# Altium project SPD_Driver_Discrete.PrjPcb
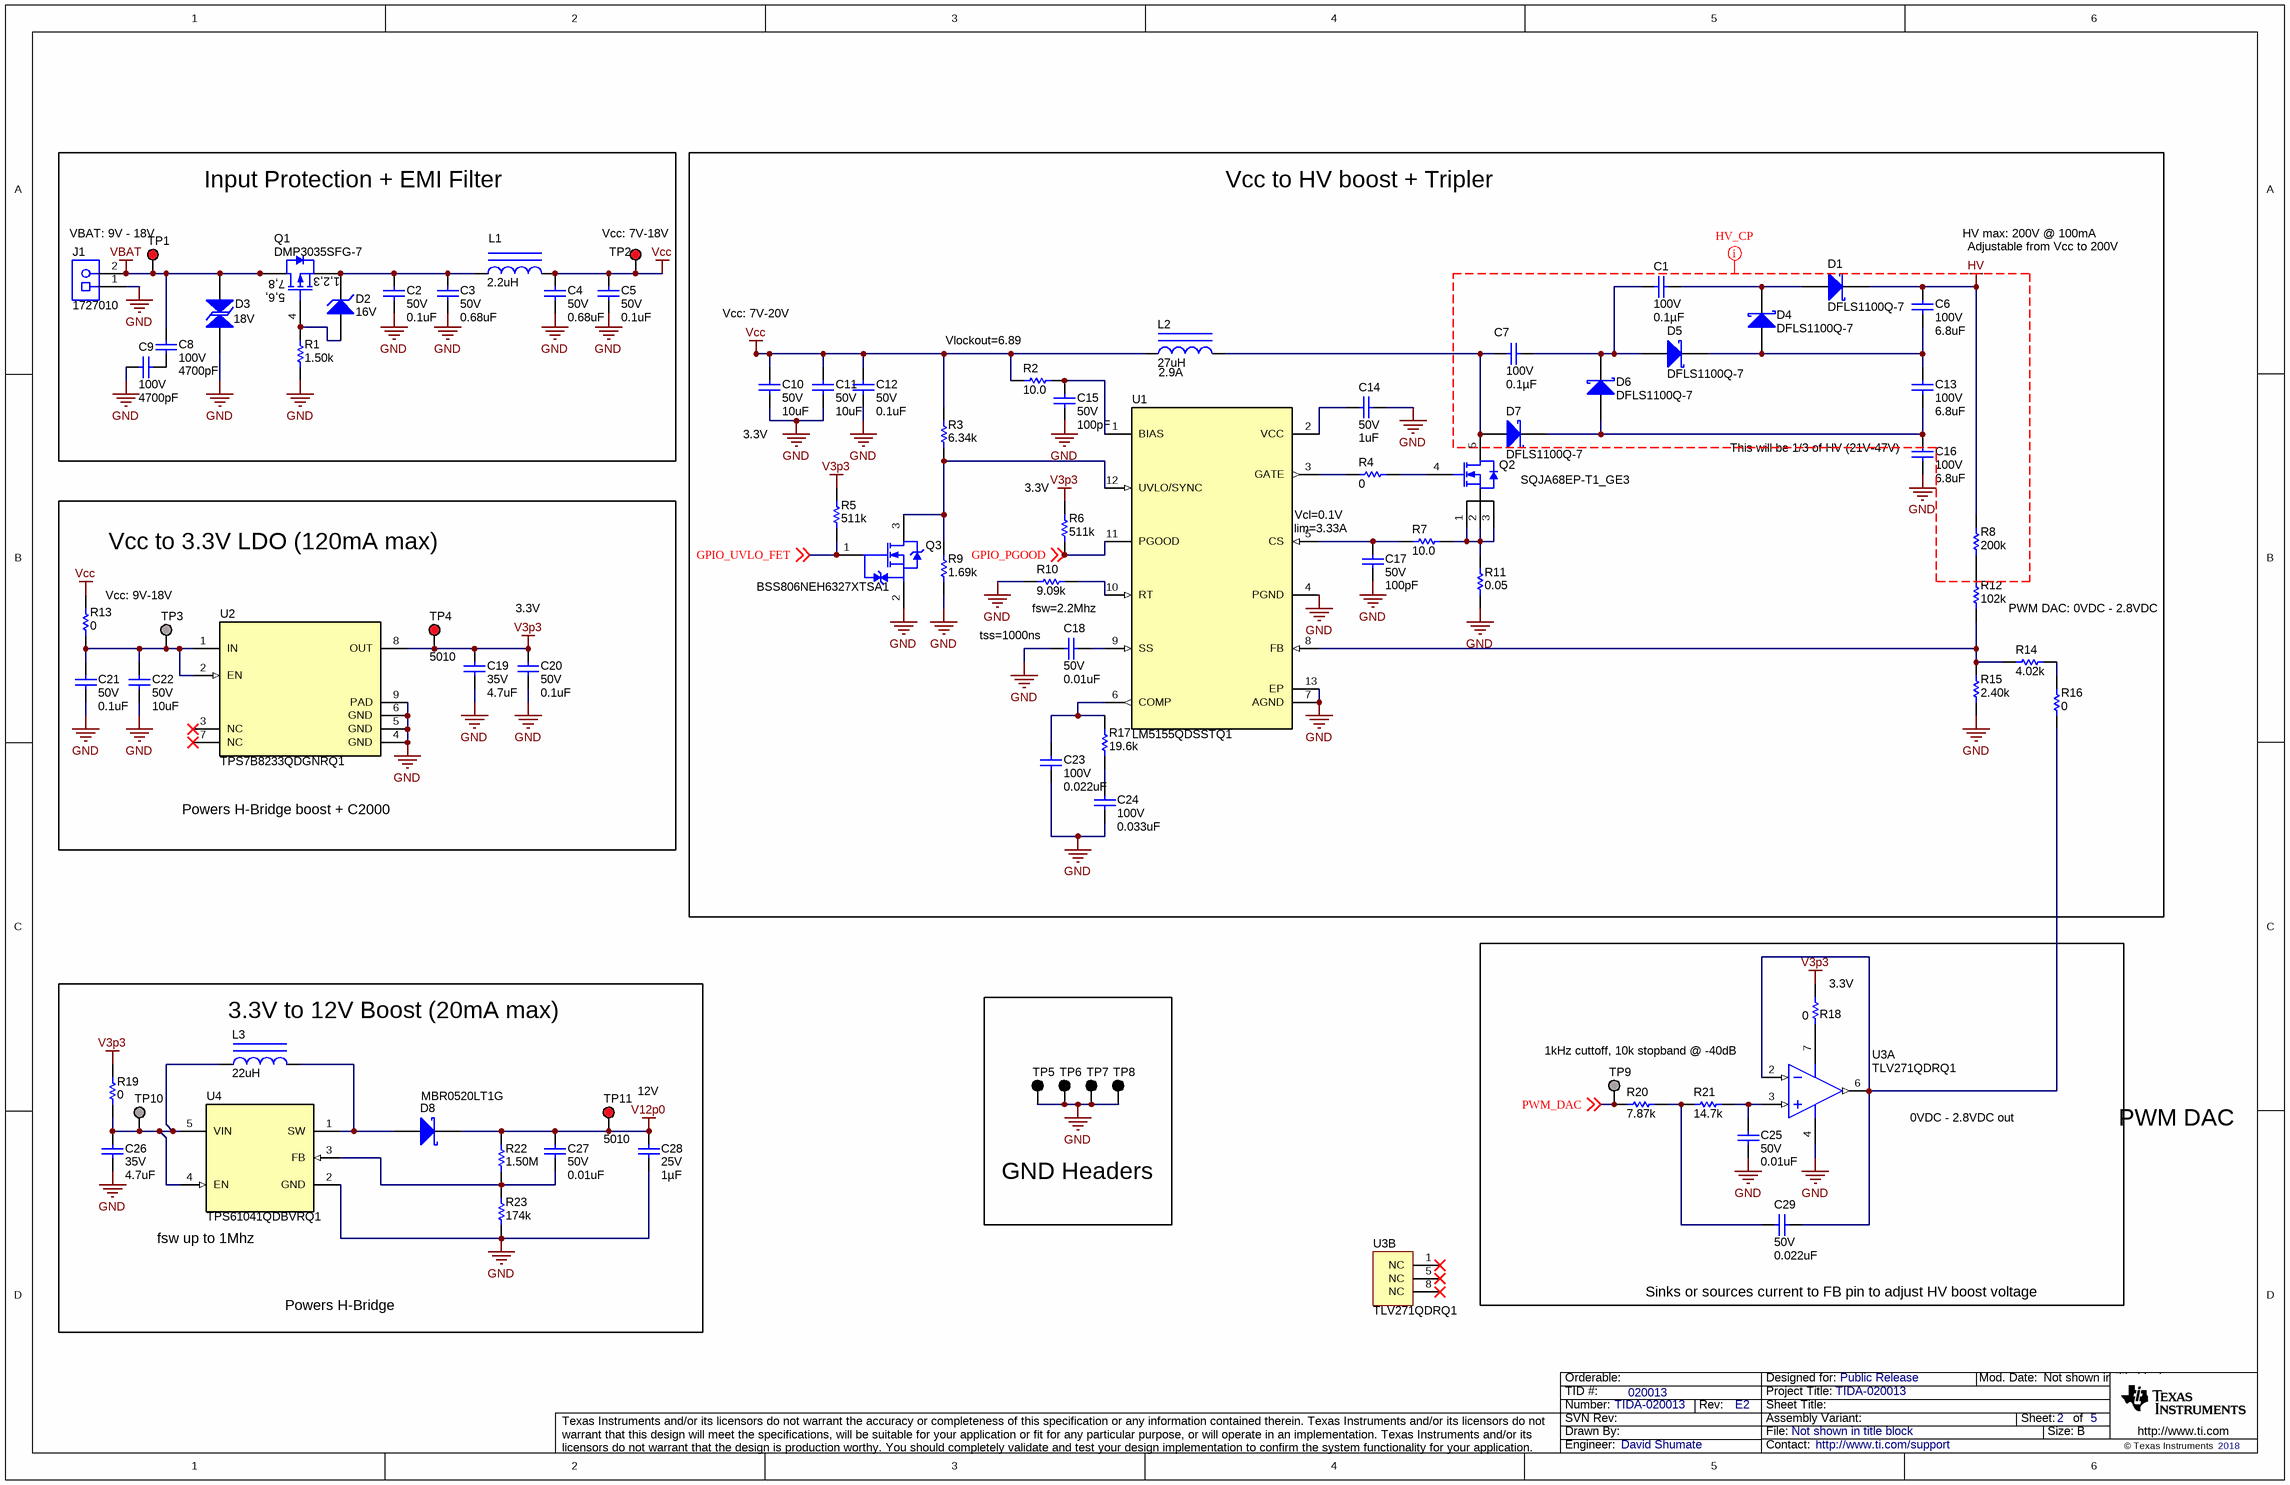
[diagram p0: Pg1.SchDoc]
CopyrightYear: 2018; PCB_Layout: David Shumate; PCB_Rev: E2; PRJ_Customer: Public Release; PRJ_Engineer: David Shumate; PRJ_Number: TIDA-020013; PRJ_Title: TIDA-020013; SCH_Rev: E2; TechSupport: http://www.ti.com/support; TID: 020013
4 sheets, 159 parts. Net scope: global (net labels, ports and power ports of the same name join across sheets).
Board file: PCB.PcbDoc
Sheets:
  Pg1.SchDoc
  Pg2.SchDoc
  Pg3.SchDoc
  EVM_Hardware.SchDoc

## Sheet Pg1.SchDoc
size 431 x 279 mm; Date: Not shown in title block; ApprovedBy: Not shown in title block; CheckedBy: Not shown in title block; Author: Not shown in title block; CompanyName: Not shown in title block; Engineer: Not shown in title block; Organization: Not shown in title block; Address1: Not shown in title block; Address2: Not shown in title block; Address3: Not shown in title block; Address4: Not shown in title block; DocumentNumber: 1; Revision: Use project parameter SCH_Rev; SheetNumber: 2; SheetTotal: 5; PageSetup: Record=PageOptions¦CenterHorizontal=True¦CenterVertical=True¦PrintScale=1.00¦XCorrection=1.00¦YCorrection=1.00¦PrintKind=0¦BorderSize=5000000¦LeftOffset=0¦BottomOffset=0¦Orientation=2¦PaperLength=1000¦PaperWidth=1000¦Scale=100¦PaperSource=15¦PrintQuality=600¦MediaType=1¦DitherType=10¦PaperKind=Letter¦PrintScaleMode=1

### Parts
C1  VDC_V: 100V  ValueDisplayed: 0.1µF  [0603]  (hidden comment: HMK107B7104KAHT)
C2  VDC_V: 50V  ValueDisplayed: 0.1uF  [0402]  (hidden comment: GCM155R71H104KE02D)
C3  VDC_V: 50V  ValueDisplayed: 0.68uF  [0805_HV]  (hidden comment: CGA4J3X7R1H684K125AB)
C4  VDC_V: 50V  ValueDisplayed: 0.68uF  [0805_HV]  (hidden comment: CGA4J3X7R1H684K125AB)
C5  VDC_V: 50V  ValueDisplayed: 0.1uF  [0402]  (hidden comment: GCM155R71H104KE02D)
C6  VDC_V: 100V  ValueDisplayed: 6.8uF  [2220_220]  (hidden comment: CGA9M3X7S2A685K200KB)
C7  VDC_V: 100V  ValueDisplayed: 0.1µF  [0603]  (hidden comment: HMK107B7104KAHT)
C8  VDC_V: 100V  ValueDisplayed: 4700pF  [0603L]  (hidden comment: CGA3E2X7R2A472K080AA)
C9  VDC_V: 100V  ValueDisplayed: 4700pF  [0603L]  (hidden comment: CGA3E2X7R2A472K080AA)
C10  VDC_V: 50V  ValueDisplayed: 10uF  [1206]  (hidden comment: CGA5L3X5R1H106M160AB)
C11  VDC_V: 50V  ValueDisplayed: 10uF  [1206]  (hidden comment: CGA5L3X5R1H106M160AB)
C12  VDC_V: 50V  ValueDisplayed: 0.1uF  [0402]  (hidden comment: GCM155R71H104KE02D)
C13  VDC_V: 100V  ValueDisplayed: 6.8uF  [2220_220]  (hidden comment: CGA9M3X7S2A685K200KB)
C14  VDC_V: 50V  ValueDisplayed: 1uF  [0805_HV1]  (hidden comment: CGA4J3X7R1H105K125AB)
C15  VDC_V: 50V  ValueDisplayed: 100pF  [0603L]  (hidden comment: CGA3E2NP01H101J080AA)
C16  VDC_V: 100V  ValueDisplayed: 6.8uF  [2220_220]  (hidden comment: CGA9M3X7S2A685K200KB)
C17  VDC_V: 50V  ValueDisplayed: 100pF  [0603L]  (hidden comment: CGA3E2NP01H101J080AA)
C18  VDC_V: 50V  ValueDisplayed: 0.01uF  [0402L]  (hidden comment: CGA2B3X7R1H103K050BB)
C19  VDC_V: 35V  ValueDisplayed: 4.7uF  [0805_HV]  (hidden comment: CGA4J1X7R1V475K125AC)
C20  VDC_V: 50V  ValueDisplayed: 0.1uF  [0402]  (hidden comment: GCM155R71H104KE02D)
C21  VDC_V: 50V  ValueDisplayed: 0.1uF  [0402]  (hidden comment: GCM155R71H104KE02D)
C22  VDC_V: 50V  ValueDisplayed: 10uF  [1206]  (hidden comment: CGA5L3X5R1H106M160AB)
C23  VDC_V: 100V  ValueDisplayed: 0.022uF  [0603L]  (hidden comment: CGA3E2X7R2A223K080AA)
C24  VDC_V: 100V  ValueDisplayed: 0.033uF  [0603L]  (hidden comment: CGA3E3X7S2A333K080AB)
C25  VDC_V: 50V  ValueDisplayed: 0.01uF  [0402]  (hidden comment: CGA2B3X7R1H103K050BB)
C26  VDC_V: 35V  ValueDisplayed: 4.7uF  [0805_HV]  (hidden comment: CGA4J1X7R1V475K125AC)
C27  VDC_V: 50V  ValueDisplayed: 0.01uF  [0402]  (hidden comment: CGA2B3X7R1H103K050BB)
C28  VDC_V: 25V  ValueDisplayed: 1µF  [0603S]  (hidden comment: CGA3E1X7R1E105K080AC)
C29  VDC_V: 50V  ValueDisplayed: 0.022uF  [0402]  (hidden comment: CGA2B3X7R1H223K050BB)
D1  DFLS1100Q-7  [PowerDI123]
D2  value 16V  [SOD-123]  (hidden comment: BZT52C16-7-F)
D3  value 18V  [SMA]  (hidden comment: P4SMA18CA-E3/61)
D4  DFLS1100Q-7  [PowerDI123]
D5  DFLS1100Q-7  [PowerDI123]
D6  DFLS1100Q-7  [PowerDI123]
D7  DFLS1100Q-7  [PowerDI123]
D8  MBR0520LT1G  [SOD-123]
J1  1727010  [PhoenixConact_1727010]
L1  ValueDisplayed: 2.2uH  [XAL5030]  (hidden comment: XAL5030-222MEB)
L2  Value2: 2.9A  ValueDisplayed: 27uH  [MSS1260T]  (hidden comment: MSS1260T-273MLB)
L3  ValueDisplayed: 22uH  [WE-MAIA_3015]  (hidden comment: 78438335220)
Q1  DMP3035SFG-7  [PowerDI3333-8]
Q2  SQJA68EP-T1_GE3  [PowerPAK_SO-8L]
Q3  BSS806NEH6327XTSA1  [SOT-23L]
R1  ValueDisplayed: 1.50k  [0603L]  (hidden comment: CRCW06031K50FKEA)
R2  ValueDisplayed: 10.0  [0603]  (hidden comment: CRCW060310R0FKEAHP)
R3  ValueDisplayed: 6.34k  [0402]  (hidden comment: CRCW04026K34FKED)
R4  ValueDisplayed: 0  [0603L]  (hidden comment: RCS06030000Z0EA)
R5  ValueDisplayed: 511k  [0402]  (hidden comment: CRCW0402511KFKED)
R6  ValueDisplayed: 511k  [0402]  (hidden comment: CRCW0402511KFKED)
R7  ValueDisplayed: 10.0  [0603L]  (hidden comment: CRCW060310R0FKEAHP)
R8  ValueDisplayed: 200k  [1206L]  (hidden comment: ERJ-8ENF2003V)
R9  ValueDisplayed: 1.69k  [0805_HV1]  (hidden comment: ERJ-6ENF1691V)
R10  ValueDisplayed: 9.09k  [0603L]  (hidden comment: CRCW06039K09FKEA)
R11  ValueDisplayed: 0.05  [0603L]  (hidden comment: ERJ-L03KF50MV)
R12  ValueDisplayed: 102k  [1206L]  (hidden comment: ERJ-8ENF1023V)
R13  ValueDisplayed: 0  [0603]  (hidden comment: RCS06030000Z0EA)
R14  ValueDisplayed: 4.02k  [0603L]  (hidden comment: CRCW06034K02FKEA)
R15  ValueDisplayed: 2.40k  [0402L]  (hidden comment: ERJ-2RKF2401X)
R16  ValueDisplayed: 0  [0402L]  (hidden comment: CRCW04020000Z0EDHP)
R17  ValueDisplayed: 19.6k  [0603L]  (hidden comment: CRCW060319K6FKEA)
R18  ValueDisplayed: 0  [0402]  (hidden comment: CRCW04020000Z0EDHP)
R19  ValueDisplayed: 0  [0603]  (hidden comment: RCS06030000Z0EA)
R20  ValueDisplayed: 7.87k  [0402]  (hidden comment: CRCW04027K87FKED)
R21  ValueDisplayed: 14.7k  [0402]  (hidden comment: CRCW040214K7FKED)
R22  ValueDisplayed: 1.50M  [0402]  (hidden comment: CRCW04021M50FKED)
R23  ValueDisplayed: 174k  [0402]  (hidden comment: CRCW0402174KFKED)
TP1  5010  [Keystone5010]  (value not drawn)
TP2  5010  [Keystone5010]  (value not drawn)
TP3  TP_SM_1MM  [TP_SM_1MM]  (value not drawn)  (no BOM)
TP4  5010  [Keystone5010]
TP5  5011  [Keystone5011]  (value not drawn)
TP6  5011  [Keystone5011]  (value not drawn)
TP7  5011  [Keystone5011]  (value not drawn)
TP8  5011  [Keystone5011]  (value not drawn)
TP9  TP_SM_1MM  [TP_SM_1MM]  (value not drawn)  (no BOM)
TP10  TP_SM_1MM  [TP_SM_1MM]  (value not drawn)  (no BOM)
TP11  5010  [Keystone5010]
U1  LM5155QDSSTQ1  [DSS0012C]
U2  TPS7B8233QDGNRQ1  [DGN0008D_N]
U3  TLV271QDRQ1  [D0008A_N]  (parts A,B of 2)
U4  TPS61041QDBVRQ1  [DBV0005A_N]

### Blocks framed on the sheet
Input Protection + EMI Filter: C2-C5 C8 C9 D2 D3 J1 L1 Q1 R1 TP1 TP2
Vcc to HV boost + Tripler: C1 C6 C7 C10-C18 C23 C24 D1 D4-D7 L2 Q2 Q3 R2-R12 R14-R17 U1
Vcc to 3.3V LDO (120mA max): C19-C22 R13 TP3 TP4 U2
3.3V to 12V Boost (20mA max): C26-C28 D8 L3 R19 R22 R23 TP10 TP11 U4
GND Headers: TP5-TP8

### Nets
GND: C2.2 C3.2 C4.2 C5.2 C9.1 C10.2 C11.2 C12.2 C14.1 C15.2 C16.2 C17.2 C18.2 C19.2 C20.2 C21.2 C22.2 C23.2 C24.2 C25.2 C26.2 C28.2 D3.2 J1.1 Q3.2(S) R1.1 R9.1 R10.1 R11.1 R15.1 R23.1 TP5.1 TP6.1 TP7.1 TP8.1 U1.4(PGND) U1.7(AGND) U1.13(EP) U2.4(GND) U2.5(GND) U2.6(GND) U2.9(PAD) U3.4(GND) U4.2(GND)
HV: C6.1 D1.1(K) R8.2
V3p3: C19.1 C20.1 R5.2 R6.2 R18.2 R19.2 TP4.1 U2.8(OUT)
V12p0: C27.1 C28.1 D8.1(K) R22.2 TP11.1
VBAT: C8.1 D3.1 J1.2 Q1.5(D) Q1.6(D) Q1.7(D) Q1.8(D) Q1.9(D) TP1.1
Vcc: C4.1 C5.1 C10.1 C11.1 C12.1 L1.2 L2.1 R2.1 R3.2 R13.2 TP2.1
GPIO_PGOOD: R6.1 U1.11(PGOOD) ; off-sheet GPIO_PGOOD
GPIO_UVLO_FET: Q3.1(G) R5.1 ; off-sheet GPIO_UVLO_FET
PWM_DAC: R20.1 TP9.1 ; off-sheet PWM_DAC
NetC1_1: C1.1 D1.2(A) D4.1(K)
NetC1_2: C1.2 C7.1 D5.2(A) D6.1(K)
NetC2_1: C2.1 C3.1 D2.1(K) L1.1 Q1.1(S) Q1.2(S) Q1.3(S)
NetC6_2: C6.2 C13.1 D4.2(A) D5.1(K)
NetC7_2: C7.2 D7.2(A) L2.2 Q2.5(D)
NetC8_2: C8.2 C9.2
NetC13_2: C13.2 C16.1 D6.2(A) D7.1(K)
NetC14_2: C14.2 U1.2(VCC)
NetC15_1: C15.1 R2.2 U1.1(BIAS)
NetC17_1: C17.1 R7.1 U1.5(CS)
NetC18_1: C18.1 U1.9(SS)
NetC21_1: C21.1 C22.1 R13.1 TP3.1 U2.1(IN) U2.2(EN)
NetC23_1: C23.1 R17.2 U1.6(COMP)
NetC24_1: C24.1 R17.1
NetC25_1: C25.1 R21.2 U3.3(IN+)
NetC26_1: C26.1 L3.1 R19.1 TP10.1 U4.4(EN) U4.5(VIN)
NetC27_2: C27.2 R22.1 R23.2 U4.3(FB)
NetC29_1: C29.1 R16.1 U3.2(IN-) U3.6(OUT)
NetC29_2: C29.2 R20.2 R21.1
NetD2_2: D2.2(A) Q1.4(G) R1.2
NetD8_2: D8.2(A) L3.2 U4.1(SW)
NetQ2_1: Q2.1(S) Q2.2(S) Q2.3(S) R7.2 R11.2
NetQ2_4: Q2.4(G) R4.2
NetQ3_3: Q3.3(D) R3.1 R9.2 U1.12(UVLO/SYNC)
NetR4_1: R4.1 U1.3(GATE)
NetR8_1: R8.1 R12.2
NetR10_2: R10.2 U1.10(RT)
NetR12_1: R12.1 R14.1 R15.2 U1.8(FB)
NetR14_2: R14.2 R16.2
NetR18_1: R18.1 U3.7(VDD)

Not connected (* = marked no-connect by the designer): U2 3(NC)* 7(NC)*; U3 1(NC)* 5(NC)* 8(NC)*

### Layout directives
net class HV_CP: GND, HV

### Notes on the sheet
- VBAT: 9V - 18V
- (near TP2) Vcc: 7V-18V
- HV max: 200V @ 100mA
- Adjustable from Vcc to 200V
- Vcc: 7V-20V
- (near R2) Vlockout=6.89
- (near C10) 3.3V
- (near R6) 3.3V
- (near C16) This will be 1/3 of HV (21V-47V)
- (near U1) Vcl=0.1V
- (near U1) Ilim=3.33A
- Vcc: 9V-18V
- 3.3V
- (near C18) tss=1000ns
- fsw=2.2Mhz
- PWM DAC: 0VDC - 2.8VDC
- Powers H-Bridge boost + C2000
- (near R18) 3.3V
- 12V
- 1kHz cuttoff, 10k stopband @ -40dB
- 0VDC - 2.8VDC out
- PWM DAC
- (near U4) fsw up to 1Mhz
- Powers H-Bridge
- Sinks or sources current to FB pin to adjust HV boost voltage

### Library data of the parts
C1 C7 = CMP-0081011-1: CAP, CERM, 0.1 µF, 100 V,+/- 10%, X7R, AEC-Q200 Grade 1, 0603; Manufacturer: Taiyo Yuden; Cap_F: 100nF; SizeAreaWB_mm2: 4.68; SizeArea_mm2: 1.28; AEC Qualified: Y; AEC Category: Q200; Value: 0.1uF; TaMax_C: 125°C; SizeZ_mm: 1; Polarized: N; TaMin_C: -55°C; SizeY_mm: 0.8; U/M: EA; SizeX_mm: 1.6
C2 C5 = CMP-0006356-2: CAP, CERM, 0.1 uF, 50 V, +/- 10%, X7R, AEC-Q200 Grade 1, 0402; Manufacturer: MuRata; TaMin_C: -55°C; Polarized: N; SizeAreaWB_mm2: 3; Value1: Unknown; U/M: EA; Value: 0.1uF; TaMax_C: 125°C; SizeZ_mm: 0.6; SizeX_mm: 1; SizeY_mm: 0.5; CompType: Capacitor; AEC Qualified: Y; Cap_F: 100nF; AEC Category: Q200
C3 C4 = CMP-0007979-2: CAP, CERM, 0.68 uF, 50 V, +/- 10%, X7R, AEC-Q200 Grade 1, 0805; Manufacturer: TDK; TaMin_C: -55°C; ESR_ohm: 0.011711; Polarized: N; SizeAreaWB_mm2: 6.75; Value1: 0.011711 ohm; U/M: EA; Value: 0.68uF; TaMax_C: 125°C; SizeZ_mm: 1.45; SizeX_mm: 2; SizeY_mm: 1.25; Cap_Case: 0805; SizeArea_mm2: 2.5; CompType: Capacitor; AEC Qualified: Y; Cap_F: 680nF; IRMS_A: 1.91098A; AEC Grade: 1; AEC Category: Q200
C6 C13 C16 = CMP-0009407-2: CAP, CERM, 6.8 uF, 100 V, +/- 10%, X7S, AEC-Q200 Grade 1, 2220; Manufacturer: TDK; TaMin_C: -55°C; ESR_ohm: 3.492m; Polarized: N; SizeAreaWB_mm2: 53.9; Value1: 0.003492 ohm; U/M: EA; Value: 6.8uF; TaMax_C: 125°C; SizeZ_mm: 2.2; SizeX_mm: 5.7; SizeY_mm: 5; SizeArea_mm2: 28.5; AEC Qualified: Y; Cap_F: 6.8µF; IRMS_A: 4.88574A; AEC Grade: 1; AEC Category: Q200
C8 C9 = CMP-0007088-4: CAP, CERM, 4700 pF, 100 V, +/- 10%, X7R, AEC-Q200 Grade 1, 0603; Manufacturer: TDK; TaMin_C: -55°C; ESR_ohm: 4.69862d; Polarized: N; SizeAreaWB_mm2: 4.68; Value1: 0.469862 ohm; U/M: EA; Value: 4700pF; TaMax_C: 125°C; SizeZ_mm: 1; SizeX_mm: 1.6; SizeY_mm: 0.8; Cap_Case: 0603; SizeArea_mm2: 1.28; CompType: Capacitor; AEC Qualified: Y; Cap_F: 4.7nF; IRMS_A: 3.2335dA; AEC Category: Q200
C10 C11 C22 = CMP-0008785-2: CAP, CERM, 10 uF, 50 V, +/- 20%, X5R, AEC-Q200 Grade 3, 1206; Manufacturer: TDK; TaMin_C: -55°C; Polarized: N; SizeAreaWB_mm2: 10.92; Value1: Unknown; U/M: EA; Value: 10uF; TaMax_C: 85°C; SizeZ_mm: 1.35; SizeX_mm: 3.2; SizeY_mm: 1.6; SizeArea_mm2: 5.12; CompType: Capacitor; AEC Qualified: Y; Cap_F: 10µF; AEC Grade: 3; AEC Category: Q200
C12 C20 C21 = CMP-0006356-2: CAP, CERM, 0.1 uF, 50 V, +/- 10%, X7R, AEC-Q200 Grade 1, 0402; Manufacturer: MuRata; TaMin_C: -55°C; Polarized: N; SizeAreaWB_mm2: 3; Value1: Unknown; U/M: EA; Value: 0.1uF; TaMax_C: 125°C; SizeZ_mm: 0.6; SizeX_mm: 1; SizeY_mm: 0.5; AEC Qualified: Y; Cap_F: 100nF; AEC Category: Q200
C14 = CMP-0007976-2: CAP, CERM, 1 uF, 50 V, +/- 10%, X7R, AEC-Q200 Grade 1, 0805; Manufacturer: TDK; TaMin_C: -55°C; ESR_ohm: 8.782m; Polarized: N; SizeAreaWB_mm2: 6.75; Value1: 0.008782 ohm; U/M: EA; Value: 1uF; TaMax_C: 125°C; SizeZ_mm: 1.45; SizeX_mm: 2; SizeY_mm: 1.25; Cap_Case: 0805; SizeArea_mm2: 2.5; CompType: Capacitor; AEC Qualified: Y; Cap_F: 1µF; IRMS_A: 2.20488A; AEC Grade: 1; AEC Category: Q200
C15 C17 = CMP-0007075-4: CAP, CERM, 100 pF, 50 V, +/- 5%, C0G/NP0, AEC-Q200 Grade 0, 0603; Manufacturer: TDK; TaMin_C: -55°C; Polarized: N; SizeAreaWB_mm2: 4.68; Value1: Unknown; U/M: EA; Value: 100pF; TaMax_C: 150°C; SizeZ_mm: 1; SizeX_mm: 1.6; SizeY_mm: 0.8; Cap_Case: 0603; SizeArea_mm2: 1.28; CompType: Capacitor; AEC Qualified: Y; AEC Grade: 0; AEC Category: Q200
C18 = CMP-0006324-2: CAP, CERM, 0.01 uF, 50 V, +/- 10%, X7R, AEC-Q200 Grade 1, 0402; Manufacturer: TDK; TaMin_C: -55°C; ESR_ohm: 3.33065d; Polarized: N; SizeAreaWB_mm2: 3; Value1: 0.333065 ohm; U/M: EA; Value: 0.01uF; TaMax_C: 125°C; SizeZ_mm: 0.6; SizeX_mm: 1; SizeY_mm: 0.5; Cap_Case: 0402; CompType: Capacitor; AEC Qualified: Y; Cap_F: 10nF; IRMS_A: 3.23373dA; AEC Category: Q200
C19 C26 = CMP-0007964-2: CAP, CERM, 4.7 uF, 35 V, +/- 10%, X7R, AEC-Q200 Grade 1, 0805; Manufacturer: TDK; TaMin_C: -55°C; ESR_ohm: 2.346m; Polarized: N; SizeAreaWB_mm2: 6.75; Value1: 0.002346 ohm; U/M: EA; Value: 4.7uF; TaMax_C: 125°C; SizeZ_mm: 1.45; SizeX_mm: 2; SizeY_mm: 1.25; Cap_Case: 0805; SizeArea_mm2: 2.5; AEC Qualified: Y; Cap_F: 4.7µF; IRMS_A: 4.26021A; AEC Grade: 1; AEC Category: Q200
C23 = CMP-0007086-4: CAP, CERM, 0.022 uF, 100 V, +/- 10%, X7R, AEC-Q200 Grade 1, 0603; Manufacturer: TDK; TaMin_C: -55°C; ESR_ohm: 0.083542; Polarized: N; SizeAreaWB_mm2: 4.68; Value1: 0.083542 ohm; U/M: EA; TaMax_C: 125°C; SizeZ_mm: 1; SizeX_mm: 1.6; SizeY_mm: 0.8; Cap_Case: 0603; SizeArea_mm2: 1.28; CompType: Capacitor; AEC Qualified: Y; Cap_F: 22nF; IRMS_A: 6.09312dA; AEC Category: Q200
C24 = CMP-0007100-4: CAP, CERM, 0.033 uF, 100 V, +/- 10%, X7S, AEC-Q200 Grade 1, 0603; Manufacturer: TDK; TaMin_C: -55°C; ESR_ohm: 1.39637d; Polarized: N; SizeAreaWB_mm2: 4.68; Value1: 0.139637 ohm; U/M: EA; TaMax_C: 125°C; SizeZ_mm: 1; SizeX_mm: 1.6; SizeY_mm: 0.8; Cap_Case: 0603; SizeArea_mm2: 1.28; CompType: Capacitor; AEC Qualified: Y; Cap_F: 33nF; IRMS_A: 4.62257dA; AEC Category: Q200
C25 C27 = CMP-0006324-2: CAP, CERM, 0.01 uF, 50 V, +/- 10%, X7R, AEC-Q200 Grade 1, 0402; Manufacturer: TDK; TaMin_C: -55°C; ESR_ohm: 3.33065d; Polarized: N; SizeAreaWB_mm2: 3; Value1: 0.333065 ohm; U/M: EA; Value: 0.01uF; TaMax_C: 125°C; SizeZ_mm: 0.6; SizeX_mm: 1; SizeY_mm: 0.5; AEC Qualified: Y; Cap_F: 10nF; IRMS_A: 3.23373dA; AEC Category: Q200
C28 = CMP-0076705-3: CAP, CERM, 1 µF, 25 V,+/- 10%, X7R, AEC-Q200 Grade 1, 0603; Manufacturer: TDK; SizeAreaWB_mm2: 4.68; SizeArea_mm2: 1.28; AEC Qualified: Y; AEC Category: Q200; Value: 1uF; TaMax_C: 125°C; SizeZ_mm: 1.0; AEC Grade: 1; Polarized: N; TaMin_C: -55°C; SizeY_mm: 0.8; U/M: EA; SizeX_mm: 1.6; Cap_Case: 1.6x0.8x0.8mm
C29 = CMP-0006328-2: CAP, CERM, 0.022 uF, 50 V, +/- 10%, X7R, AEC-Q200 Grade 1, 0402; Manufacturer: TDK; TaMin_C: -55°C; ESR_ohm: 1.41987d; Polarized: N; SizeAreaWB_mm2: 3; Value1: 0.141987 ohm; U/M: EA; TaMax_C: 125°C; SizeZ_mm: 0.6; SizeX_mm: 1; SizeY_mm: 0.5; AEC Qualified: Y; Cap_F: 22nF; IRMS_A: 4.51393dA; AEC Category: Q200
D1 D4-D7 = CMP-0074797-1: Diode, Schottky, 100 V, 1 A, AEC-Q101, PowerDI123; Manufacturer: Diodes Inc.; Io_A: 1A; SizeAreaWB_mm2: 13.066; Vr_V: 100V; TJmax_C: 175°C; U/M: EA; Value: 100V; SizeZ_mm: 0.98; SizeX_mm: 3.7; SizeY_mm: 1.78; Vf_V: 7.7dV; Value2: .77V; SizeArea_mm2: 6.586; AEC Qualified: Y; AEC Category: Q101; RJC_CperW: 21.0
D2 = CMP-0005769-2: Diode, Zener, 16 V, 500 mW, AEC-Q101, SOD-123; Manufacturer: Diodes Inc.; Power_W: 500mW; SizeAreaWB_mm2: 13.095; Value1: 0.5W; RJA_CperW: 338; U/M: EA; SizeZ_mm: 1.35; SizeX_mm: 3.85; SizeY_mm: 1.7; SizeArea_mm2: 6.545; AEC Qualified: Y; AEC Category: Q101
D3 = CMP-0005445-2: Diode, TVS, Bi, 18 V, 25.2 Vc, AEC-Q101, SMA; Manufacturer: Vishay-Semiconductor; Power_W: 3.3W; SizeAreaWB_mm2: 37.3428; RJA_CperW: 120; U/M: EA; SizeZ_mm: 2.87; SizeX_mm: 5.59; SizeY_mm: 2.92; SizeArea_mm2: 16.3228; AEC Qualified: Y; AEC Category: Q101
D8 = CMP-0028524-1: Diode, Schottky, 20 V, 0.5 A, SOD-123; Manufacturer: ON Semiconductor; Io_A: 5dA; Green_Lifecycle: Active; SizeAreaWB_mm2: 13.095; Vr_V: 20V; Green_REACh: Passed; Value1: 0.5A; TJmax_C: 125°C; U/M: EA; Value: 20V; SizeZ_mm: 1.35; SizeX_mm: 3.85; SizeY_mm: 1.7; Vf_V: 3.85dV; Value2: 0.385V; SizeArea_mm2: 6.545; AEC Category: Q101; RJC_CperW: 150
J1 = CMP-0055472-1: Conn Term Block, 2POS, 3.81mm, TH; Manufacturer: Phoenix Contact; CT: TRUE; Green_REACh: Incomplete; CompType: Terminal Block; CNHeader: FALSE; Green_Lifecycle: Not Set
L1 = CMP-0061001-2: Inductor, Shielded, Composite, 2.2 µH, 9.2 A, 0.01 ohm, AEC-Q200 Grade 1, SMD; Manufacturer: Coilcraft; Isat: 12.9A @ 30% inductance drop; Irms: 9.2A @ 40C rise; Green_Lifecycle: Not Set; SizeAreaWB_mm2: 54.4544; DCR_ohm: 0.01; Green_REACh: Incomplete; Value: 2.2uH; Imax_A: 9.2A; SizeZ_mm: 3.1; SizeX_mm: 5.28; SizeY_mm: 5.48; SizeArea_mm2: 28.9344; Ind_H: 2.2µH; AEC Qualified: 1; AEC Category: Q200; AEC Grade: Y
L2 = CMP-0061500-2: Inductor, Shielded Drum Core, Ferrite, 27 uH, 2.9 A, 0.05 ohm, SMD; Manufacturer: Coilcraft; Isat: 4.68A @ 30% inductance drop; Irms: 2.9A @ 40C rise; Green_Lifecycle: Not Set; SizeAreaWB_mm2: 204.49; DCR_ohm: 0.05; Green_REACh: Incomplete; Value: 27uH; SizeZ_mm: 6; SizeX_mm: 12.3; SizeArea_mm2: 151.29; Ind_H: 27µH; AEC Category: Q200
L3 = CMP-0064681-2: Inductor, Shielded, Powdered Iron, 22 uH, 0.6 A, 1.04 ohm, AEC-Q200 Grade 1, SMD; Manufacturer: Wurth Elektronik; Isat: 1.6A @ 20% inductance drop; Irms: 0.6A @ 40C rise; SizeAreaWB_mm2: 16; DCR_ohm: 1.04; Value: 22uH; Imax_A: 6dA; SizeZ_mm: 1.5; SizeX_mm: 3; Value2: 0.6A; SizeArea_mm2: 9; Ind_H: 22µH; AEC Qualified: Y; AEC Grade: 1; AEC Category: Q200
Q1 = CMP-0000041-2: MOSFET, P-CH, -30 V, -8.5 A, AEC-Q101, 8-PowerVDFN; Alternate Manufacturer: None; Manufacturer: Diodes Inc.; SizeZ_mm: 0.8; ChType: P; Value2: 35.5 nC; VdsMax_V: -30V; SizeX_mm: 3.3; Vgs_V: -25V; QgTyp_nC: 35.5; AEC Qualified: Y; Value: -30V; SizeArea_mm2: 10.89; AEC Category: Q101; IdsMax_A: -8.5A; SizeAreaWB_mm2: 18.49; U/M: EA
Q2 = CMP-0080929-1: MOSFET, N-CH, 100 V, 14 A, AEC-Q101, PowerPAK_SO-8L; Alternate Manufacturer: None; Manufacturer: Vishay-Siliconix; Rdson45_ohm: 1.17d; QgTyp_nC: 4.7; SizeAreaWB_mm2: 58.1095; Vgs_V: 20V; Value1: 0.117 ohm; VdsMax_V: 100V; Value: 100V; IdsMax_A: 14A; SizeZ_mm: 1.14; SizeX_mm: 6.15; SizeY_mm: 5.13; Value2: 4.7 nC; SizeArea_mm2: 31.5495; ChType: N; AEC Qualified: Y; AEC Category: Q101
Q3 = CMP-0077248-1: MOSFET, N-CH, 20 V, 2.3 A, AEC-Q101, SOT-23; Manufacturer: Infineon Technologies; Alternate Manufacturer: None; ChType: N; QgTyp_nC: 1.7; SizeAreaWB_mm2: 14.0; SizeArea_mm2: 7.5; IdsMax_A: 2.3A; AEC Qualified: Y; VdsMax_V: 20V; Vgs_V: 8V; AEC Category: Q101; Value: 20V; SizeZ_mm: 1.1; SizeY_mm: 3.0; Value2: 1.7 nC; U/M: EA; Value1: ? ohm; SizeX_mm: 2.5
R1 = CMP-0022126-4: RES, 1.50 k, 1%, 0.1 W, AEC-Q200 Grade 0, 0603; Manufacturer: Vishay-Dale; Power_W: 100mW; TempCo: 100 ppm/C; Value_Code: 1k50; Value: 1.50k; EIA_Code: E96; Res_ohm: 1.5k; SizeX_mm: 1.6; SizeY_mm: 0.8; SizeZ_mm: 1; Value2: 0.1W; SizeArea_mm2: 1.28; CompType: Resistor; AEC Qualified: Y; VDC_V: 75V; AEC Category: Q200; AEC Grade: 0
R2 = CMP-0022004-4: RES, 10.0, 1%, 0.25 W, AEC-Q200 Grade 0, 0603; Manufacturer: Vishay-Dale; Power_W: 250mW; TempCo: 100 ppm/C; Value_Code: 10R0; Value: 10.0; EIA_Code: E96; Res_ohm: 10; SizeX_mm: 1.6; SizeY_mm: 0.8; SizeZ_mm: 1; Value2: 0.25W; SizeArea_mm2: 1.28; AEC Qualified: Y; VDC_V: 75V; AEC Category: Q200; AEC Grade: 0
R3 = CMP-0026514-2: RES, 6.34 k, 1%, 0.063 W, AEC-Q200 Grade 0, 0402; Manufacturer: Vishay-Dale; Power_W: 63mW; TempCo: 100 ppm/C; Value_Code: 6k34; Value: 6.34k; EIA_Code: E96; SizeX_mm: 1; SizeY_mm: 0.5; SizeZ_mm: 0.6; Value2: 0.063W; AEC Qualified: Y; VDC_V: 50V; AEC Category: Q200; AEC Grade: 0
R4 = CMP-0081973-1: RES, 0, 0%, 0.25 W, AEC-Q200 Grade 0, 0603; Manufacturer: Vishay-Dale; SizeAreaWB_mm2: 4.68; SizeArea_mm2: 1.28; AEC Qualified: Y; AEC Category: Q200; Value: 0; SizeZ_mm: 1; SizeY_mm: 0.8; Power_W: 250mW; Value2: 0.25W; CompType: Resistor; SizeX_mm: 1.6
R5 R6 = CMP-0026435-2: RES, 511 k, 1%, 0.063 W, AEC-Q200 Grade 0, 0402; Manufacturer: Vishay-Dale; Power_W: 63mW; TempCo: 100 ppm/C; Value: 511k; EIA_Code: E96; SizeX_mm: 1; SizeY_mm: 0.5; SizeZ_mm: 0.6; Value2: 0.063W; AEC Qualified: Y; VDC_V: 50V; AEC Category: Q200; AEC Grade: 0
R7 = CMP-0022004-4: RES, 10.0, 1%, 0.25 W, AEC-Q200 Grade 0, 0603; Manufacturer: Vishay-Dale; Power_W: 250mW; TempCo: 100 ppm/C; Value_Code: 10R0; Value: 10.0; EIA_Code: E96; Res_ohm: 10; SizeX_mm: 1.6; SizeY_mm: 0.8; SizeZ_mm: 1; Value2: 0.25W; SizeArea_mm2: 1.28; CompType: Resistor; AEC Qualified: Y; VDC_V: 75V; AEC Category: Q200; AEC Grade: 0
R8 = CMP-0017437-3: RES, 200 k, 1%, 0.25 W, AEC-Q200 Grade 0, 1206; Manufacturer: Panasonic; Power_W: 250mW; TempCo: 100 ppm/C; Value: 200k; EIA_Code: E96; SizeX_mm: 3.2; SizeY_mm: 1.6; SizeZ_mm: 1.35; Value2: 0.25W; SizeArea_mm2: 5.12; CompType: Resistor; AEC Qualified: Y; VDC_V: 200V; AEC Category: Q200; AEC Grade: 0; SizeAreaWB_mm2: 10.92
R9 = CMP-0021591-3: RES, 1.69 k, 1%, 0.125 W, AEC-Q200 Grade 0, 0805; Manufacturer: Panasonic; Power_W: 125mW; TempCo: 100 ppm/C; Value_Code: 1k69; Value: 1.69k; EIA_Code: E96; SizeX_mm: 2; SizeY_mm: 1.25; SizeZ_mm: 1.45; Value2: 0.125W; SizeArea_mm2: 2.5; CompType: Resistor; AEC Qualified: Y; AEC Category: Q200; AEC Grade: 0; SizeAreaWB_mm2: 6.75
R10 = CMP-0022665-4: RES, 9.09 k, 1%, 0.1 W, AEC-Q200 Grade 0, 0603; Manufacturer: Vishay-Dale; Power_W: 100mW; TempCo: 100 ppm/C; Value_Code: 9k09; Value: 9.09k; EIA_Code: E96; SizeX_mm: 1.6; SizeY_mm: 0.8; SizeZ_mm: 1; Value2: 0.1W; SizeArea_mm2: 1.28; CompType: Resistor; AEC Qualified: Y; VDC_V: 75V; AEC Category: Q200; AEC Grade: 0
R11 = CMP-0022727-3: RES, 0.05, 1%, 0.1 W, AEC-Q200 Grade 1, 0603; Manufacturer: Panasonic; Power_W: 100mW; TempCo: 200 ppm/C; Value_Code: R050; Value: 0.05; EIA_Code: E96; SizeX_mm: 1.6; SizeY_mm: 0.8; SizeZ_mm: 1; Value2: 0.1W; SizeArea_mm2: 1.28; CompType: Resistor; AEC Qualified: Y; AEC Category: Q200; SizeAreaWB_mm2: 4.68
R12 = CMP-0017290-3: RES, 102 k, 1%, 0.25 W, AEC-Q200 Grade 0, 1206; Manufacturer: Panasonic; Power_W: 250mW; TempCo: 100 ppm/C; Value: 102k; EIA_Code: E96; SizeX_mm: 3.2; SizeY_mm: 1.6; SizeZ_mm: 1.35; Value2: 0.25W; SizeArea_mm2: 5.12; CompType: Resistor; AEC Qualified: Y; VDC_V: 200V; AEC Category: Q200; AEC Grade: 0; SizeAreaWB_mm2: 10.92
R13 R19 = CMP-0081973-1: RES, 0, 0%, 0.25 W, AEC-Q200 Grade 0, 0603; Manufacturer: Vishay-Dale; SizeAreaWB_mm2: 4.68; SizeArea_mm2: 1.28; AEC Qualified: Y; AEC Category: Q200; Value: 0; SizeZ_mm: 1; SizeY_mm: 0.8; Power_W: 250mW; Value2: 0.25W; SizeX_mm: 1.6
R14 = CMP-0022449-4: RES, 4.02 k, 1%, 0.1 W, AEC-Q200 Grade 0, 0603; Manufacturer: Vishay-Dale; Power_W: 100mW; TempCo: 100 ppm/C; Value_Code: 4k02; Value: 4.02k; EIA_Code: E96; SizeX_mm: 1.6; SizeY_mm: 0.8; SizeZ_mm: 1; Value2: 0.1W; SizeArea_mm2: 1.28; CompType: Resistor; AEC Qualified: Y; VDC_V: 75V; AEC Category: Q200; AEC Grade: 0
R15 = CMP-0026685-1: RES, 2.40 k, 1%, 0.1 W, AEC-Q200 Grade 0, 0402; Manufacturer: Panasonic; Power_W: 100mW; TempCo: 100 ppm/C; Value_Code: 2k40; U/M: EA; Value: 2.40k; Res_ohm: 2.4k; SizeX_mm: 1; SizeY_mm: 0.5; SizeZ_mm: 0.6; Value2: 0.1W; CompType: Resistor; AEC Qualified: Y; AEC Grade: 0; AEC Category: Q200
R16 R18 = CMP-0081856-1: RES, 0, 0%, 0.2 W, AEC-Q200 Grade 0, 0402; Manufacturer: Vishay-Dale; SizeAreaWB_mm2: 3; SizeArea_mm2: 0.5; AEC Qualified: Y; AEC Category: Q200; Value: 0; SizeZ_mm: 0.6; Power_W: 200mW; VDC_V: 50V; Value2: 0.2W; CompType: Resistor; SizeX_mm: 1
R17 = CMP-0022106-4: RES, 19.6 k, 1%, 0.1 W, AEC-Q200 Grade 0, 0603; Manufacturer: Vishay-Dale; Power_W: 100mW; TempCo: 100 ppm/C; Value_Code: 19k6; Value: 19.6k; EIA_Code: E96; SizeX_mm: 1.6; SizeY_mm: 0.8; SizeZ_mm: 1; Value2: 0.1W; SizeArea_mm2: 1.28; CompType: Resistor; AEC Qualified: Y; VDC_V: 75V; AEC Category: Q200; AEC Grade: 0
R20 = CMP-0026557-2: RES, 7.87 k, 1%, 0.063 W, AEC-Q200 Grade 0, 0402; Manufacturer: Vishay-Dale; Power_W: 63mW; TempCo: 100 ppm/C; Value_Code: 7k87; Value: 7.87k; EIA_Code: E96; SizeX_mm: 1; SizeY_mm: 0.5; SizeZ_mm: 0.6; Value2: 0.063W; AEC Qualified: Y; VDC_V: 50V; AEC Grade: 0; AEC Category: Q200
R21 = CMP-0026017-3: RES, 14.7 k, 1%, 0.063 W, AEC-Q200 Grade 0, 0402; Manufacturer: Vishay-Dale; Power_W: 63mW; TempCo: 100 ppm/C; Value_Code: 14k7; Value: 14.7k; EIA_Code: E96; SizeX_mm: 1; SizeY_mm: 0.5; SizeZ_mm: 0.6; Value2: 0.063W; AEC Qualified: Y; VDC_V: 50V; AEC Category: Q200; AEC Grade: 0
R22 = CMP-0026117-2: RES, 1.50 M, 1%, 0.063 W, AEC-Q200 Grade 0, 0402; Manufacturer: Vishay-Dale; Power_W: 63mW; TempCo: 100 ppm/C; Value_Code: 1M50; Value: 1.50Meg; EIA_Code: E96; Res_ohm: 1.5M; SizeX_mm: 1; SizeY_mm: 0.5; SizeZ_mm: 0.6; Value2: 0.063W; AEC Qualified: Y; VDC_V: 50V; AEC Category: Q200; AEC Grade: 0
R23 = CMP-0026046-3: RES, 174 k, 1%, 0.063 W, AEC-Q200 Grade 0, 0402; Manufacturer: Vishay-Dale; Power_W: 63mW; TempCo: 100 ppm/C; Value: 174k; EIA_Code: E96; SizeX_mm: 1; SizeY_mm: 0.5; SizeZ_mm: 0.6; Value2: 0.063W; AEC Qualified: Y; VDC_V: 50V; AEC Category: Q200; AEC Grade: 0
TP1 TP2 TP4 TP11 = CMP-0055147-1: Test Point, Multipurpose, Red, TH; Manufacturer: Keystone; CNHeader: FALSE; Green_Lifecycle: Active; Green_REACh: Passed; ContactFinish: Silver; CT: TRUE
TP3 TP9 TP10 = CMP-0003825-1: 1mm Test Point, SMT; Manufacturer: Any
TP5-TP8 = CMP-0055148-1: Test Point, Multipurpose, Black, TH; Manufacturer: Keystone; CNHeader: FALSE; Green_Lifecycle: Active; Green_REACh: Passed; ContactFinish: Silver; CT: TRUE
U1 = CMP-0081538-1: Automotive Grade 2.2-MHz Wide Input Non-synchronous Boost Controller, DSS0012C (WSON-12); Alternate PartNumber: LM5155QDSSRQ1; Alternate Manufacturer: Texas Instruments; SizeAreaWB_mm2: 12; SizeZ_mm: 0.8; SizeX_mm: 2; SizeY_mm: 3; SizeArea_mm2: 6; CompType: IC; AEC Qualified: Y; AEC Category: Q200
U2 = CMP-0013312-4: 300mA High-Voltage Ultra-Low-Iq Low-Dropout (LDO) Regulator, DGN0008D (VSSOP-8); Manufacturer: Texas Instruments; SizeX_mm: 5.05; SizeY_mm: 3.1; CompType: IC; SizeZ_mm: 1.1; SizeArea_mm2: 15.655; SizeAreaWB_mm2: 35.955; AEC Category: Q200; AEC Qualified: Y
U3 = CMP-0042688-1: Automotive Catalog 550 uA/Ch, 3 MHz, Rail-to-Rail Output Operational Amplifier, 2.7 to 16 V, -40 to 125 degC, 8-pin SOIC (D8), Green (RoHS & no Sb/Br); Manufacturer: Texas Instruments; IIB(Max)(pA): 60; Slew Rate(Typ)(V/us): 2.4; Packing: LARGE T&R; Total Supply Voltage(Max)(+5V is 5, +/-5V is 10): 16; Total Supply Voltage(Min)(+5V is 5, +/-5V is 10): 2.7; GBW(Typ)(MHz): 3; CMRR(Min)(dB): 58; Vio (25C)(Max)(mV): 5; Sub Family: Low Supply Voltage Amplifier (<=2.7V), Precision Amplifier; Number of Channels: 1; Offset Drift(Typ)(uV/C): 2; Iq per channel(Max)(mA): 0.66
U4 = CMP-0034799-1: Automotive Catalog Low Power DC / DC Boost Conveter, 1.8 to 6 V, -40 to 125 degC, 5-pin SOT23 (DBV5), Green (RoHS & no Sb/Br); Manufacturer: Texas Instruments; Dimming: TRUE; SubFamily: White LED Driver; Vin(Min)(V): 1.8; Vin(Max)(V): 6; Switching Frequency(Max)(kHz): 1000; Iout(Max)(A): 0.05; Iq(Typ)(mA): 0.028

## Sheet Pg2.SchDoc
size 431 x 279 mm; Date: Not shown in title block; ApprovedBy: Not shown in title block; CheckedBy: Not shown in title block; Author: Not shown in title block; CompanyName: Not shown in title block; Engineer: Not shown in title block; Organization: Not shown in title block; Address1: Not shown in title block; Address2: Not shown in title block; Address3: Not shown in title block; Address4: Not shown in title block; DocumentNumber: 1; Revision: Use project parameter SCH_Rev; SheetNumber: 3; SheetTotal: 5; PageSetup: Record=PageOptions¦CenterHorizontal=True¦CenterVertical=True¦PrintScale=1.00¦XCorrection=1.00¦YCorrection=1.00¦PrintKind=0¦BorderSize=5000000¦LeftOffset=0¦BottomOffset=0¦Orientation=2¦PaperLength=1000¦PaperWidth=1000¦Scale=100¦PaperSource=15¦PrintQuality=600¦MediaType=1¦DitherType=10¦PaperKind=Letter¦PrintScaleMode=1
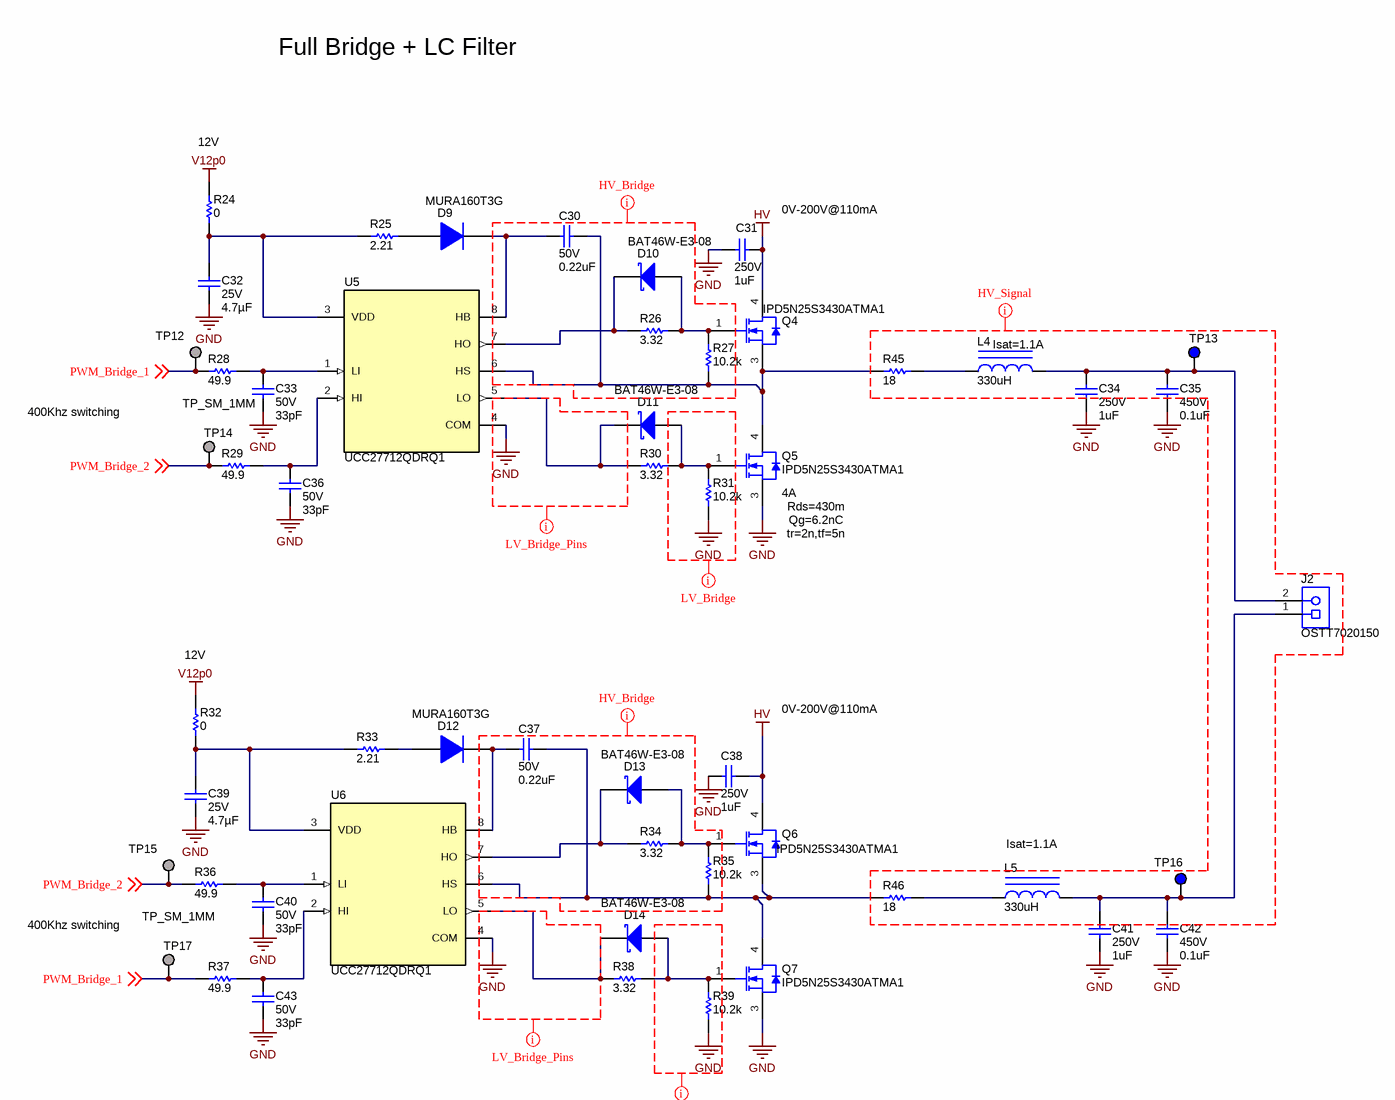
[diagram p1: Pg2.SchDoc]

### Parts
C30  VDC_V: 50V  ValueDisplayed: 0.22uF  [0805_HV]  (hidden comment: CGA4J2X7R1H224K125AA)
C31  VDC_V: 250V  ValueDisplayed: 1uF  [1825_254]  (hidden comment: 1825PC105KAT1A)
C32  VDC_V: 25V  ValueDisplayed: 4.7µF  [0805L]  (hidden comment: CGA4J1X7R1E475K125AC)
C33  VDC_V: 50V  ValueDisplayed: 33pF  [0402L]  (hidden comment: C0402C330J5GACAUTO)
C34  VDC_V: 250V  ValueDisplayed: 1uF  [1825_254]  (hidden comment: 1825PC105KAT1A)
C35  VDC_V: 450V  ValueDisplayed: 0.1uF  [1206_180]  (hidden comment: CGA5L4X7T2W104M160AA)
C36  VDC_V: 50V  ValueDisplayed: 33pF  [0402L]  (hidden comment: C0402C330J5GACAUTO)
C37  VDC_V: 50V  ValueDisplayed: 0.22uF  [0805_HV]  (hidden comment: CGA4J2X7R1H224K125AA)
C38  VDC_V: 250V  ValueDisplayed: 1uF  [1825_254]  (hidden comment: 1825PC105KAT1A)
C39  VDC_V: 25V  ValueDisplayed: 4.7µF  [0805L]  (hidden comment: CGA4J1X7R1E475K125AC)
C40  VDC_V: 50V  ValueDisplayed: 33pF  [0402L]  (hidden comment: C0402C330J5GACAUTO)
C41  VDC_V: 250V  ValueDisplayed: 1uF  [1825_254]  (hidden comment: 1825PC105KAT1A)
C42  VDC_V: 450V  ValueDisplayed: 0.1uF  [1206_180]  (hidden comment: CGA5L4X7T2W104M160AA)
C43  VDC_V: 50V  ValueDisplayed: 33pF  [0402L]  (hidden comment: C0402C330J5GACAUTO)
D9  MURA160T3G  [SMA]
D10  BAT46W-E3-08  [SOD-123]
D11  BAT46W-E3-08  [SOD-123]
D12  MURA160T3G  [SMA]
D13  BAT46W-E3-08  [SOD-123]
D14  BAT46W-E3-08  [SOD-123]
J2  OSTT7020150  [On-Shore_OSTT7020150]
L4  ValueDisplayed: 330uH  [SRR1260A]  (hidden comment: SRR1260A-331K)
L5  ValueDisplayed: 330uH  [SRR1260A]  (hidden comment: SRR1260A-331K)
Q4  IPD5N25S3430ATMA1  [DPAK]
Q5  IPD5N25S3430ATMA1  [DPAK]
Q6  IPD5N25S3430ATMA1  [DPAK]
Q7  IPD5N25S3430ATMA1  [DPAK]
R24  ValueDisplayed: 0  [0402]  (hidden comment: CRCW04020000Z0EDHP)
R25  ValueDisplayed: 2.21  [0402]  (hidden comment: CRCW04022R21FKED)
R26  ValueDisplayed: 3.32  [0402]  (hidden comment: CRCW04023R32FKED)
R27  ValueDisplayed: 10.2k  [0402]  (hidden comment: CRCW040210K2FKED)
R28  ValueDisplayed: 49.9  [0402]  (hidden comment: CRCW040249R9FKED)
R29  ValueDisplayed: 49.9  [0402]  (hidden comment: CRCW040249R9FKED)
R30  ValueDisplayed: 3.32  [0402]  (hidden comment: CRCW04023R32FKED)
R31  ValueDisplayed: 10.2k  [0402]  (hidden comment: CRCW040210K2FKED)
R32  ValueDisplayed: 0  [0402]  (hidden comment: CRCW04020000Z0EDHP)
R33  ValueDisplayed: 2.21  [0402]  (hidden comment: CRCW04022R21FKED)
R34  ValueDisplayed: 3.32  [0402]  (hidden comment: CRCW04023R32FKED)
R35  ValueDisplayed: 10.2k  [0402]  (hidden comment: CRCW040210K2FKED)
R36  ValueDisplayed: 49.9  [0402]  (hidden comment: CRCW040249R9FKED)
R37  ValueDisplayed: 49.9  [0402]  (hidden comment: CRCW040249R9FKED)
R38  ValueDisplayed: 3.32  [0402]  (hidden comment: CRCW04023R32FKED)
R39  ValueDisplayed: 10.2k  [0402]  (hidden comment: CRCW040210K2FKED)
R45  ValueDisplayed: 18  [1206]  (hidden comment: CRCW120618R0JNEA)
R46  ValueDisplayed: 18  [1206]  (hidden comment: CRCW120618R0JNEA)
TP12  TP_SM_1MM  [TP_SM_1MM]  (value not drawn)  (no BOM)
TP13  5127  [Keystone5127]  (value not drawn)
TP14  TP_SM_1MM  [TP_SM_1MM]  (no BOM)
TP15  TP_SM_1MM  [TP_SM_1MM]  (value not drawn)  (no BOM)
TP16  5127  [Keystone5127]  (value not drawn)
TP17  TP_SM_1MM  [TP_SM_1MM]  (no BOM)
U5  UCC27712QDRQ1  [D0008A_N]
U6  UCC27712QDRQ1  [D0008A_N]

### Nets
GND: C31.2 C32.2 C33.2 C34.2 C35.2 C36.2 C38.2 C39.2 C40.2 C41.2 C42.2 C43.2 Q5.3(S) Q7.3(S) R31.1 R39.1 U5.4(COM) U6.4(COM)
HV: C31.1 C38.1 Q4.4(D) Q6.4(D)
V12p0: R24.2 R32.2
PWM_Bridge_1: R28.1 R37.1 TP12.1 TP17.1 ; off-sheet PWM_Bridge_1
PWM_Bridge_2: R29.1 R36.1 TP14.1 TP15.1 ; off-sheet PWM_Bridge_2
NetC30_1: C30.1 Q4.3(S) Q5.4(D) R27.1 R45.1 U5.6(HS)
NetC30_2: C30.2 D9.1(K) U5.8(HB)
NetC32_1: C32.1 R24.1 R25.1 U5.3(VDD)
NetC33_1: C33.1 R28.2 U5.1(LI)
NetC34_1: C34.1 C35.1 J2.2 L4.2 TP13.1
NetC36_1: C36.1 R29.2 U5.2(HI)
NetC37_1: C37.1 Q6.3(S) Q7.4(D) R35.1 R46.1 U6.6(HS)
NetC37_2: C37.2 D12.1(K) U6.8(HB)
NetC39_1: C39.1 R32.1 R33.1 U6.3(VDD)
NetC40_1: C40.1 R36.2 U6.1(LI)
NetC41_1: C41.1 C42.1 J2.1 L5.2 TP16.1
NetC43_1: C43.1 R37.2 U6.2(HI)
NetD9_2: D9.2(A) R25.2
NetD10_1: D10.1(K) R26.1 U5.7(HO)
NetD10_2: D10.2(A) Q4.1(G) R26.2 R27.2
NetD11_1: D11.1(K) R30.1 U5.5(LO)
NetD11_2: D11.2(A) Q5.1(G) R30.2 R31.2
NetD12_2: D12.2(A) R33.2
NetD13_1: D13.1(K) R34.1 U6.7(HO)
NetD13_2: D13.2(A) Q6.1(G) R34.2 R35.2
NetD14_1: D14.1(K) R38.1 U6.5(LO)
NetD14_2: D14.2(A) Q7.1(G) R38.2 R39.2
NetL4_1: L4.1 R45.2
NetL5_1: L5.1 R46.2

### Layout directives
net class HV_Bridge: GND
net class LV_Bridge: GND
net class LV_Bridge_Pins: GND
net class HV_Signal: GND

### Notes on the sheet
- Full Bridge + LC Filter
- (near R24) 12V
- (near C31) 0V-200V@110mA
- (near L4) Isat=1.1A
- 400Khz switching
- (near Q5) 4A
- (near Q5) Rds=430m
- (near Q5) Qg=6.2nC
- tr=2n,tf=5n
- (near R32) 12V
- 0V-200V@110mA
- (near L5) Isat=1.1A

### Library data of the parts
C30 C37 = CMP-0007967-2: CAP, CERM, 0.22 uF, 50 V, +/- 10%, X7R, AEC-Q200 Grade 1, 0805; Manufacturer: TDK; TaMin_C: -55°C; ESR_ohm: 0.016949; Polarized: N; SizeAreaWB_mm2: 6.75; Value1: 0.016949 ohm; U/M: EA; Value: 0.22uF; TaMax_C: 125°C; SizeZ_mm: 1.45; SizeX_mm: 2; SizeY_mm: 1.25; Cap_Case: 0805; SizeArea_mm2: 2.5; AEC Qualified: Y; Cap_F: 220nF; IRMS_A: 1.59611A; AEC Grade: 1; AEC Category: Q200
C31 C34 C38 C41 = CMP-0009302-2: CAP, CERM, 1 uF, 250 V, +/- 10%, X7R, 1825; Manufacturer: AVX; TaMin_C: -55°C; Polarized: N; SizeAreaWB_mm2: 54.6; Value1: Unknown; U/M: EA; Value: 1uF; TaMax_C: 125°C; SizeZ_mm: 2.54; SizeX_mm: 4.5; SizeY_mm: 6.4; Cap_Case: 1825; SizeArea_mm2: 28.8; Cap_F: 1µF; AEC Category: Q200
C32 C39 = CMP-0076706-1: CAP, CERM, 4.7 µF, 25 V,+/- 10%, X7R, AEC-Q200 Grade 1, 0805; Manufacturer: TDK; SizeAreaWB_mm2: 6.75; SizeArea_mm2: 2.5; AEC Qualified: Y; AEC Category: Q200; Value: 4.7uF; TaMax_C: 125°C; SizeZ_mm: 1.45; AEC Grade: 1; Polarized: N; TaMin_C: -55°C; SizeY_mm: 1.25; U/M: EA; SizeX_mm: 2.0; Cap_Case: 2x1.25x1.25mm
C33 C36 C40 C43 = CMP-0079151-1: CAP, CERM, 33 pF, 50 V,+/- 5%, C0G, AEC-Q200 Grade 1, 0402; Manufacturer: Kemet; SizeAreaWB_mm2: 3; SizeArea_mm2: 0.5; AEC Qualified: Y; AEC Category: Q200; Value: 33pF; TaMax_C: 125°C; SizeZ_mm: 0.6; AEC Grade: 1; Polarized: N; TaMin_C: -55°C; U/M: EA; CompType: Capacitor; Cap_Case: 0402
C35 C42 = CMP-0008797-2: CAP, CERM, 0.1 uF, 450 V, +/- 20%, X7T, AEC-Q200 Grade 1, 1206; Manufacturer: TDK; TaMin_C: -55°C; Polarized: N; SizeAreaWB_mm2: 10.92; Value1: Unknown; U/M: EA; Value: 0.1uF; TaMax_C: 125°C; SizeZ_mm: 1.8; SizeX_mm: 3.2; SizeY_mm: 1.6; Cap_Case: 1206; SizeArea_mm2: 5.12; AEC Qualified: Y; Cap_F: 100nF; AEC Grade: 1; AEC Category: Q200
D9 D12 = CMP-0029033-1: Diode, Ultrafast, 600 V, 1 A, AEC-Q101, SMA; Manufacturer: ON Semiconductor; Io_A: 1A; Green_Lifecycle: Active; SizeAreaWB_mm2: 37.3428; Vr_V: 600V; Green_REACh: Passed; TJmax_C: 175°C; U/M: EA; Value: 600V; SizeZ_mm: 2.87; SizeX_mm: 5.59; SizeY_mm: 2.92; Vf_V: 1.05V; SizeArea_mm2: 16.3228; AEC Qualified: Y; AEC Category: Q101
D10 D11 D13 D14 = CMP-0080760-1: Diode, Schottky, 100 V, 0.15 A, AEC-Q101, SOD-123; Manufacturer: Vishay-Semiconductor; Io_A: 1.5dA; SizeAreaWB_mm2: 13.095; Vr_V: 100V; Value1: 0.15A; TJmax_C: 125°C; Value: 100V; SizeZ_mm: 1.35; SizeX_mm: 3.85; SizeY_mm: 1.7; Vf_V: 1V; SizeArea_mm2: 6.545; AEC Qualified: Y; AEC Category: Q101
J2 = CMP-0075360-1: Terminal Block, 6.35mm, 2x1, TH; Manufacturer: On-Shore Technology; CNHeader: False; Current_A: 30A; Gender: Female; Cert_CULUS: Y; Voltage_V: 300V; Row_Count: 1; Pitch_mm: 6.35; CT: True
L4 L5 = CMP-0056393-1: Inductor, Shielded Drum Core, Ferrite, 330 uH, 1.1 A, 0.58 ohm, AEC-Q200 Grade 1, SMD; Manufacturer: Bourns; Isat: 1.1A @ 25% inductance drop; Irms: 1.15A @ 40C rise; SizeAreaWB_mm2: 210.25; DCR_ohm: 5.8d; Value: 330uH; Imax_A: 1.1A; SizeZ_mm: 6.5; SizeX_mm: 12.5; SizeArea_mm2: 156.25; Ind_H: 330µH; AEC Qualified: Y; AEC Grade: 1; AEC Category: Q200
Q4-Q7 = CMP-0082696-1: MOSFET, N-CH, 250 V, 5 A, AEC-Q101, DPAK; Manufacturer: Infineon Technologies; Alternate Manufacturer: None; ChType: N; QgTyp_nC: 4.7; SizeAreaWB_mm2: 101.7114; SizeArea_mm2: 64.8114; IdsMax_A: 5A; AEC Qualified: Y; VdsMax_V: 250V; Vgs_V: 20V; AEC Category: Q101; Value: 250V; SizeZ_mm: 2.29; ChMode: Enhancement; SizeY_mm: 6.54; Value2: 4.7 nC; Value1: ? ohm; SizeX_mm: 9.91
R24 R32 = CMP-0081856-1: RES, 0, 0%, 0.2 W, AEC-Q200 Grade 0, 0402; Manufacturer: Vishay-Dale; SizeAreaWB_mm2: 3; SizeArea_mm2: 0.5; AEC Qualified: Y; AEC Category: Q200; Value: 0; SizeZ_mm: 0.6; Power_W: 200mW; VDC_V: 50V; Value2: 0.2W; SizeX_mm: 1
R25 R33 = CMP-0026266-2: RES, 2.21, 1%, 0.063 W, AEC-Q200 Grade 0, 0402; Manufacturer: Vishay-Dale; Power_W: 63mW; TempCo: 100 ppm/C; Value_Code: 2R21; Value: 2.21; EIA_Code: E96; SizeX_mm: 1; SizeY_mm: 0.5; SizeZ_mm: 0.6; Value2: 0.063W; AEC Qualified: Y; VDC_V: 50V; AEC Category: Q200; AEC Grade: 0
R26 R30 R34 R38 = CMP-0026357-2: RES, 3.32, 1%, 0.063 W, AEC-Q200 Grade 0, 0402; Manufacturer: Vishay-Dale; Power_W: 63mW; TempCo: 100 ppm/C; Value_Code: 3R32; Value: 3.32; SizeX_mm: 1; SizeY_mm: 0.5; SizeZ_mm: 0.6; Value2: 0.063W; AEC Qualified: Y; EIA_Code: E96; VDC_V: 50V; AEC Category: Q200; AEC Grade: 0
R27 R31 R35 R39 = CMP-0025959-3: RES, 10.2 k, 1%, 0.063 W, AEC-Q200 Grade 0, 0402; Manufacturer: Vishay-Dale; Power_W: 63mW; TempCo: 100 ppm/C; Value_Code: 10k2; Value: 10.2k; EIA_Code: E96; SizeX_mm: 1; SizeY_mm: 0.5; SizeZ_mm: 0.6; Value2: 0.063W; AEC Qualified: Y; VDC_V: 50V; AEC Category: Q200; AEC Grade: 0
R28 R29 R36 R37 = CMP-0026404-2: RES, 49.9, 1%, 0.063 W, AEC-Q200 Grade 0, 0402; Manufacturer: Vishay-Dale; Power_W: 63mW; TempCo: 100 ppm/C; Value_Code: 49R9; Value: 49.9; EIA_Code: E96; SizeX_mm: 1; SizeY_mm: 0.5; SizeZ_mm: 0.6; Value2: 0.063W; AEC Qualified: Y; VDC_V: 50V; AEC Category: Q200; AEC Grade: 0
R45 R46 = CMP-0018602-3: RES, 18, 5%, 0.25 W, AEC-Q200 Grade 0, 1206; Manufacturer: Vishay-Dale; Power_W: 250mW; TempCo: 200 ppm/C; Value_Code: 18R0; Value: 18; EIA_Code: E24; SizeX_mm: 3.2; SizeY_mm: 1.6; SizeZ_mm: 1.35; Value2: 0.25W; SizeArea_mm2: 5.12; AEC Qualified: Y; VDC_V: 200V; AEC Category: Q200; AEC Grade: 0
TP12 TP14 TP15 TP17 = CMP-0003825-1: 1mm Test Point, SMT; Manufacturer: Any
TP13 TP16 = CMP-0055156-1: Test Point, Multipurpose, Blue, TH; Manufacturer: Keystone; CNHeader: FALSE; Green_Lifecycle: Active; Green_REACh: Passed; ContactFinish: Silver; CT: TRUE
U5 U6 = CMP-0065057-2: 620-V High-Side Low-Side Gate Driver with 2.5A Peak Output and RobustDrive, D0008A (SOIC-8); Manufacturer: Texas Instruments; SizeX_mm: 4.9; SizeY_mm: 6.2; CompType: IC; SizeZ_mm: 1.75; SizeArea_mm2: 30.38; SizeAreaWB_mm2: 56.58; U/M: EA

## Sheet Pg3.SchDoc
size 431 x 279 mm; Date: Not shown in title block; ApprovedBy: Not shown in title block; CheckedBy: Not shown in title block; Author: Not shown in title block; CompanyName: Not shown in title block; Engineer: Not shown in title block; Organization: Not shown in title block; Address1: Not shown in title block; Address2: Not shown in title block; Address3: Not shown in title block; Address4: Not shown in title block; DocumentNumber: 1; Revision: Use project parameter SCH_Rev; SheetNumber: 4; SheetTotal: 5; PageSetup: Record=PageOptions¦CenterHorizontal=True¦CenterVertical=True¦PrintScale=1.00¦XCorrection=1.00¦YCorrection=1.00¦PrintKind=0¦BorderSize=5000000¦LeftOffset=0¦BottomOffset=0¦Orientation=2¦PaperLength=1000¦PaperWidth=1000¦Scale=100¦PaperSource=15¦PrintQuality=600¦MediaType=1¦DitherType=10¦PaperKind=Letter¦PrintScaleMode=1
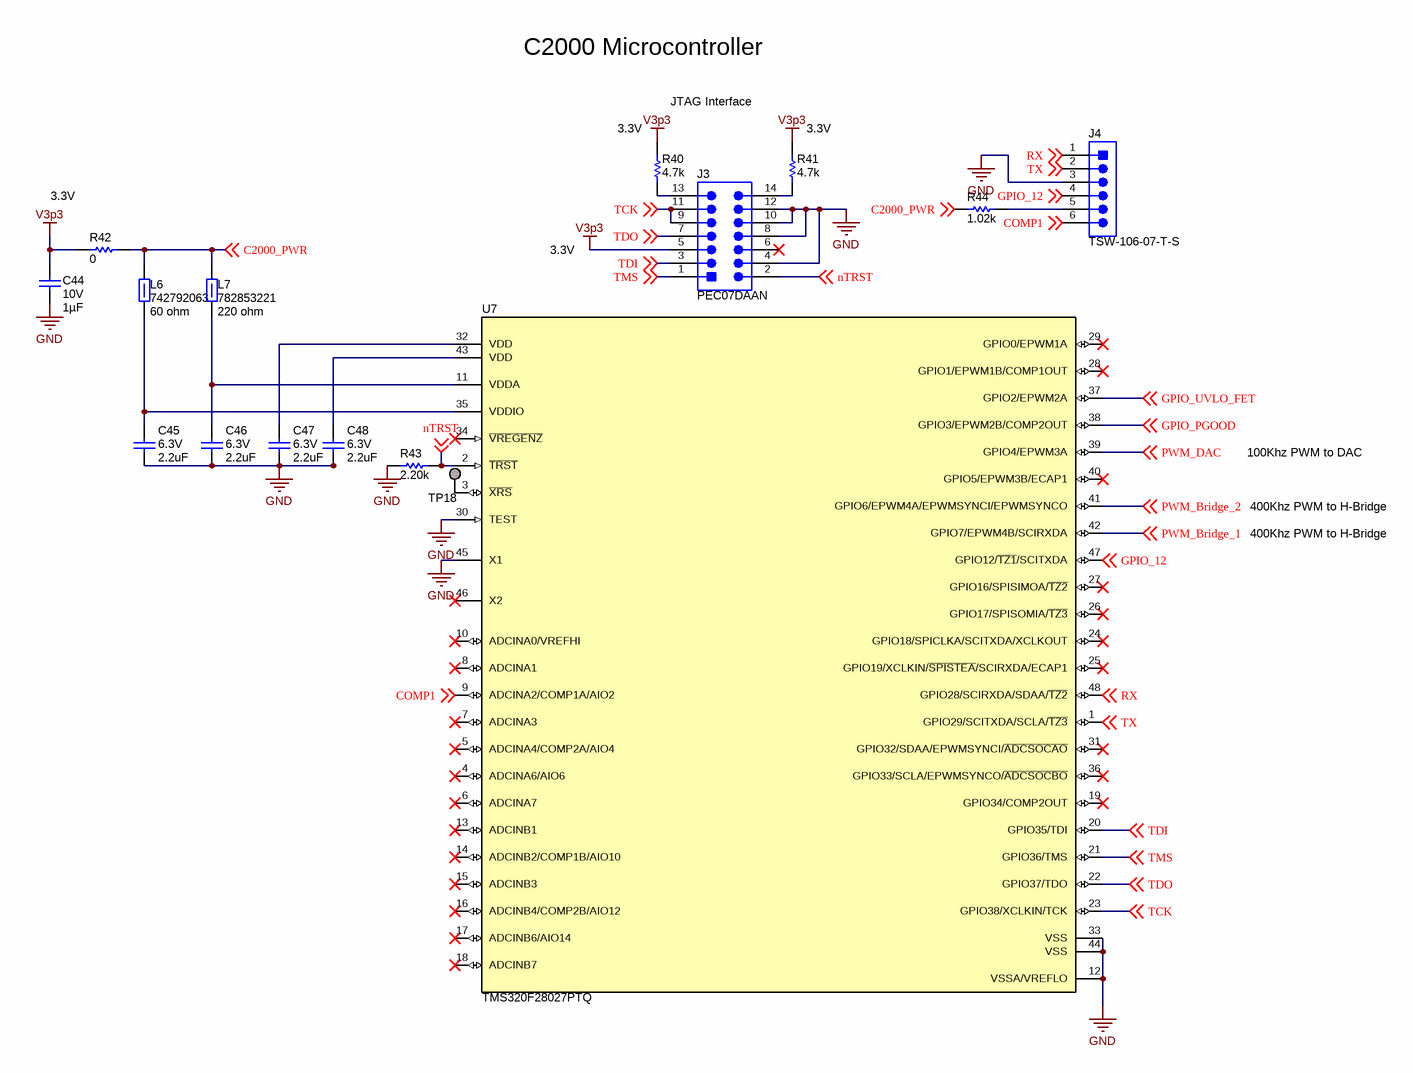
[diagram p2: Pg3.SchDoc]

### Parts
C44  VDC_V: 10V  ValueDisplayed: 1µF  [0603]  (hidden comment: CL10B105KP8VPNC)
C45  VDC_V: 6.3V  ValueDisplayed: 2.2uF  [0603]  (hidden comment: GCM188R70J225KE22D)
C46  VDC_V: 6.3V  ValueDisplayed: 2.2uF  [0603]  (hidden comment: GCM188R70J225KE22D)
C47  VDC_V: 6.3V  ValueDisplayed: 2.2uF  [0603]  (hidden comment: GCM188R70J225KE22D)
C48  VDC_V: 6.3V  ValueDisplayed: 2.2uF  [0603]  (hidden comment: GCM188R70J225KE22D)
J3  PEC07DAAN  [CONN_PEC07DAAN]
J4  TSW-106-07-T-S  [Samtec_TSW-106-07-T-S]
L6  742792063  ValueDisplayed: 60 ohm  [0805_HV]
L7  782853221  ValueDisplayed: 220 ohm  [0805_HV]
R40  ValueDisplayed: 4.7k  [0603]  (hidden comment: CRCW06034K70JNEA)
R41  ValueDisplayed: 4.7k  [0603]  (hidden comment: CRCW06034K70JNEA)
R42  ValueDisplayed: 0  [0402]  (hidden comment: CRCW04020000Z0EDHP)
R43  ValueDisplayed: 2.20k  [0402]  (hidden comment: RMCF0402FT2K20)
R44  ValueDisplayed: 1.02k  [0402]  (hidden comment: CRCW04021K02FKED)
TP18  TP_SM_1MM  [TP_SM_1MM]  (value not drawn)  (no BOM)
U7  TMS320F28027PTQ  [PT0048A_N]

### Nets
GND: C44.2 C45.2 C46.2 C47.2 C48.2 J3.4 J3.8 J3.10 J3.12 J4.3 R43.1 U7.12(VSSA/VREFLO) U7.30(TEST) U7.33(VSS) U7.44(VSS) U7.45(X1)
V3p3: C44.1 J3.5 R40.2 R41.2 R42.1
C2000_PWR: L6.2 L7.2 R42.2 R44.1 ; off-sheet C2000_PWR
COMP1: J4.6 U7.9(ADCINA2/COMP1A/AIO2) ; off-sheet COMP1
GPIO_12: J4.4 U7.47(GPIO12/~{TZ1}/SCITXDA) ; off-sheet GPIO_12
GPIO_PGOOD: U7.38(GPIO3/EPWM2B/COMP2OUT) ; off-sheet GPIO_PGOOD
GPIO_UVLO_FET: U7.37(GPIO2/EPWM2A) ; off-sheet GPIO_UVLO_FET
nTRST: J3.2 R43.2 U7.2(~{TRST}) ; off-sheet nTRST
PWM_Bridge_1: U7.42(GPIO7/EPWM4B/SCIRXDA) ; off-sheet PWM_Bridge_1
PWM_Bridge_2: U7.41(GPIO6/EPWM4A/EPWMSYNCI/EPWMSYNCO) ; off-sheet PWM_Bridge_2
PWM_DAC: U7.39(GPIO4/EPWM3A) ; off-sheet PWM_DAC
RX: J4.1 U7.48(GPIO28/SCIRXDA/SDAA/~{TZ2}) ; off-sheet RX
TCK: J3.9 J3.11 U7.23(GPIO38/XCLKIN/TCK) ; off-sheet TCK
TDI: J3.3 U7.20(GPIO35/TDI) ; off-sheet TDI
TDO: J3.7 U7.22(GPIO37/TDO) ; off-sheet TDO
TMS: J3.1 U7.21(GPIO36/TMS) ; off-sheet TMS
TX: J4.2 U7.1(GPIO29/SCITXDA/SCLA/~{TZ3}) ; off-sheet TX
NetC45_1: C45.1 L6.1 U7.35(VDDIO)
NetC46_1: C46.1 L7.1 U7.11(VDDA)
NetC47_1: C47.1 U7.32(VDD)
NetC48_1: C48.1 U7.43(VDD)
NetJ3_13: J3.13 R40.1
NetJ3_14: J3.14 R41.1
NetJ4_5: J4.5 R44.2
NetTP18_1: TP18.1 U7.3(~{XRS})

Not connected (* = marked no-connect by the designer): J3 6*; U7 4(ADCINA6/AIO6)* 5(ADCINA4/COMP2A/AIO4)* 6(ADCINA7)* 7(ADCINA3)* 8(ADCINA1)* 10(ADCINA0/VREFHI)* 13(ADCINB1)* 14(ADCINB2/COMP1B/AIO10)* 15(ADCINB3)* 16(ADCINB4/COMP2B/AIO12)* 17(ADCINB6/AIO14)* 18(ADCINB7)* 19(GPIO34/COMP2OUT)* 24(GPIO18/SPICLKA/SCITXDA/XCLKOUT)* 25(GPIO19/XCLKIN/~{SPISTEA}/SCIRXDA/ECAP1)* 26(GPIO17/SPISOMIA/~{TZ3})* 27(GPIO16/SPISIMOA/~{TZ2})* 28(GPIO1/EPWM1B/COMP1OUT)* 29(GPIO0/EPWM1A)* 31(GPIO32/SDAA/EPWMSYNCI/~{ADCSOCAO})* 34(~{VREGENZ})* 36(GPIO33/SCLA/EPWMSYNCO/~{ADCSOCBO})* 40(GPIO5/EPWM3B/ECAP1)* 46(X2)*

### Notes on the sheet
- C2000 Microcontroller
- JTAG Interface
- (near R40) 3.3V
- (near R41) 3.3V
- 3.3V
- 100Khz PWM to DAC
- 400Khz PWM to H-Bridge

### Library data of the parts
C44 = CMP-0081512-1: CAP, CERM, 1 µF, 10 V,+/- 10%, X7R, AEC-Q200 Grade 1, 0603; Manufacturer: Samsung; SizeAreaWB_mm2: 4.68; SizeArea_mm2: 1.28; AEC Qualified: Y; AEC Category: Q200; Value: 1uF; TaMax_C: 125°C; SizeZ_mm: 1; Polarized: N; TaMin_C: -55°C; SizeY_mm: 0.8; U/M: EA; SizeX_mm: 1.6
C45-C48 = CMP-0007134-5: CAP, CERM, 2.2 uF, 6.3 V, +/- 10%, X7R, AEC-Q200 Grade 1, 0603; Manufacturer: MuRata; TaMin_C: -55°C; Polarized: N; SizeAreaWB_mm2: 4.68; Value1: Unknown; U/M: EA; Value: 2.2uF; TaMax_C: 125°C; SizeZ_mm: 1; SizeX_mm: 1.6; SizeY_mm: 0.8; SizeArea_mm2: 1.28; AEC Qualified: Y; Cap_F: 2.2µF; AEC Category: Q200
J3 = CMP-0002339-2: Header, 100mil, 7x2, Tin, TH; Manufacturer: Sullins Connector Solutions; Current_A: 3A; Green_Lifecycle: Active; Shrouded: N; Gender: Male; Green_REACh: Passed; Voltage_V: 1.8kV; Row_Count: 2; RowSpacing_mm: 2.54; Cert_UL: Y
J4 = CMP-0055604-2: Header, 100mil, 6x1, Tin, TH; Manufacturer: Samtec; Cert_VDE: N; Current_A: 6.3A; Gender: Male; Cert_CSA: Y; Voltage_V: 550V; Row_Count: 1; Pitch_mm: 2.54
L6 = CMP-0003093-1: Ferrite Bead, 60 ohm @ 100 MHz, 3 A, 0805; Manufacturer: Wurth Elektronik; Ztyp@1GHz_Ohm: 95.384; ZTyp@100MHz_Ohm: 60; SizeAreaWB_mm2: 6.75; DCR_ohm: 0.025; Value1: 0.025 ohm; Value: 60 ohm; Imax_A: 3A; SizeZ_mm: 1.45; SizeX_mm: 2; SizeY_mm: 1.25; SizeArea_mm2: 2.5
L7 = CMP-0003297-1: Ferrite Bead, 220 ohm @ 100 MHz, 2 A, 0805; Manufacturer: Wurth Elektronik; Ztyp@1GHz_Ohm: 126.015; ZTyp@100MHz_Ohm: 220; SizeAreaWB_mm2: 6.75; DCR_ohm: 0.05; Value1: 0.05 ohm; Value: 220 ohm; Imax_A: 2A; SizeZ_mm: 1.45; SizeX_mm: 2; SizeY_mm: 1.25; SizeArea_mm2: 2.5
R40 R41 = CMP-0025817-4: RES, 4.7 k, 5%, 0.1 W, AEC-Q200 Grade 0, 0603; Manufacturer: Vishay-Dale; Power_W: 100mW; TempCo: 200 ppm/C; Value_Code: 4k70; Value: 4.7k; EIA_Code: E24; SizeX_mm: 1.6; SizeY_mm: 0.8; SizeZ_mm: 1; Value2: 0.1W; SizeArea_mm2: 1.28; AEC Qualified: Y; VDC_V: 75V; AEC Category: Q200; AEC Grade: 0
R42 = CMP-0081856-1: as R24 on sheet Pg2
R43 = CMP-0026758-1: RES, 2.20 k, 1%, 0.063 W, AEC-Q200 Grade 0, 0402; Manufacturer: Stackpole Electronics Inc; Power_W: 63mW; TempCo: 100 ppm/C; Value_Code: 2k20; U/M: EA; Value: 2.20k; Res_ohm: 2.2k; SizeX_mm: 1; SizeY_mm: 0.5; SizeZ_mm: 0.6; Value2: 0.063W; AEC Qualified: Y; VDC_V: 50V; AEC Grade: 0; AEC Category: Q200
R44 = CMP-0026072-3: RES, 1.02 k, 1%, 0.063 W, AEC-Q200 Grade 0, 0402; Manufacturer: Vishay-Dale; Power_W: 63mW; TempCo: 100 ppm/C; Value_Code: 1k02; Value: 1.02k; EIA_Code: E96; SizeX_mm: 1; SizeY_mm: 0.5; SizeZ_mm: 0.6; Value2: 0.063W; AEC Qualified: Y; VDC_V: 50V; AEC Category: Q200; AEC Grade: 0
TP18 = CMP-0003825-1: 1mm Test Point, SMT; Manufacturer: Any
U7 = CMP-0082224-1: Piccolo Microcontroller, PT0048A (LQFP-48); Alternate PartNumber: TMS320F28027PTQR; Alternate Manufacturer: Texas Instruments; SizeAreaWB_mm2: 121; SizeZ_mm: 1.6; SizeX_mm: 9; SizeArea_mm2: 81; CompType: IC; AEC Qualified: N; AEC Category: Q200

## Sheet EVM_Hardware.SchDoc
size 431 x 279 mm; Date: Not shown in title block; ApprovedBy: Not shown in title block; CheckedBy: Not shown in title block; Author: Not shown in title block; CompanyName: Not shown in title block; Engineer: Not shown in title block; Organization: Not shown in title block; Address1: Not shown in title block; Address2: Not shown in title block; Address3: Not shown in title block; Address4: Not shown in title block; DocumentNumber: 1; Revision: Use project parameter SCH_Rev; SheetNumber: 5; SheetTotal: 5; PageSetup: Record=PageOptions¦CenterHorizontal=True¦CenterVertical=True¦PrintScale=1.00¦XCorrection=1.00¦YCorrection=1.00¦PrintKind=0¦BorderSize=5000000¦LeftOffset=0¦BottomOffset=0¦Orientation=2¦PaperLength=1000¦PaperWidth=1000¦Scale=100¦PaperSource=15¦PrintQuality=600¦MediaType=1¦DitherType=10¦PaperKind=Letter¦PrintScaleMode=1
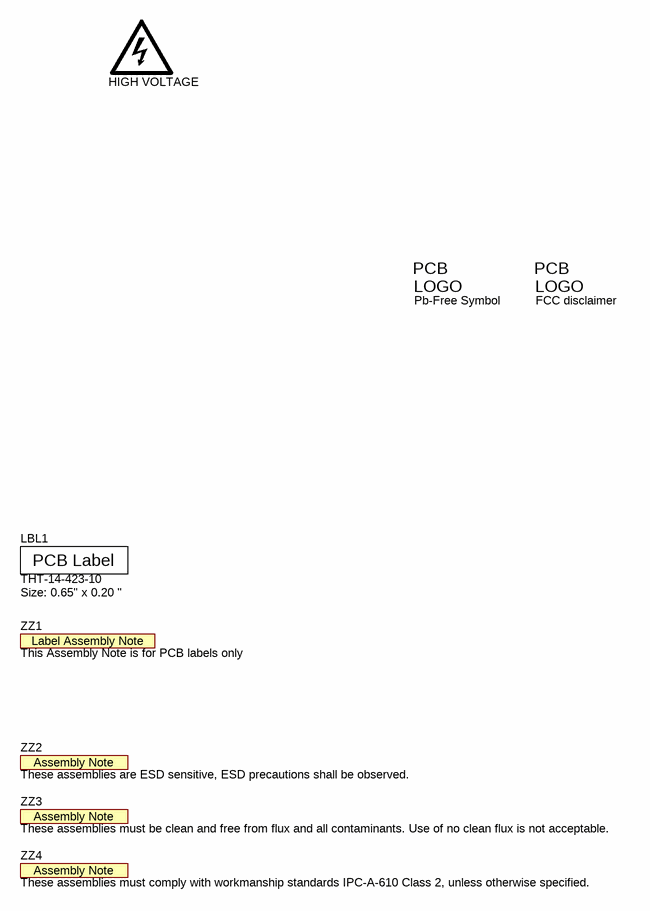
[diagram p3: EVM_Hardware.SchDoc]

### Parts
HIGH_VOLTAGE  DANGER HIGH VOLTAGE  [IEC_HighVoltage_Large]  (value not drawn)  (no BOM)
LBL1  THT-14-423-10  Note: Size: 0.65" x 0.20 "  [Label_650x200]
Logo2  Pb-Free Symbol  [Pb-Free_Overlay_Small]  (no BOM)
Logo3  FCC disclaimer  [FCC_disclaimer]  (no BOM)
ZZ1  This Assembly Note is for PCB labels only  [AssemblyNoteLabel]  (no BOM)
ZZ2  These assemblies are ESD sensitive, ESD precautions shall be observed.  [AssemblyNote]  (no BOM)
ZZ3  These assemblies must be clean and free from flux and all contaminants. Use of no clean flux is not acceptable.  [AssemblyNote]  (no BOM)
ZZ4  These assemblies must comply with workmanship standards IPC-A-610 Class 2, unless otherwise specified.  [AssemblyNote]  (no BOM)

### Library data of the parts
HIGH_VOLTAGE = IEC_HighVoltage: IEC 61010-1 High Voltage Warning; SymbolCreator: a0412235
LBL1 = CMP-0003625-1: Thermal Transfer Printable Labels, 0.650" W x 0.200" H - 10,000 per roll; Manufacturer: Brady; CompType: Label
Logo2 = CMP-0074839-1: SymbolCreator: a0412235; Library Reference: Logo
Logo3 = CMP-0074847-1: FCC_disclaimer; Library Reference: Logo
ZZ1 = CMP-0003616-3
ZZ2 = CMP-0077236-1
ZZ3 = CMP-0077237-1
ZZ4 = CMP-0077238-1

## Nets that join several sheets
GND: Pg1 (44 pins), Pg2 (18 pins), Pg3 (16 pins)
HV: Pg1 (C6.1 D1.1 R8.2), Pg2 (C31.1 C38.1 Q4.4 Q6.4)
V3p3: Pg1 (8 pins), Pg3 (5 pins)
V12p0: Pg1 (5 pins), Pg2 (R24.2 R32.2)
GPIO_PGOOD: Pg1 (R6.1 U1.11), Pg3 (U7.38)
GPIO_UVLO_FET: Pg1 (Q3.1 R5.1), Pg3 (U7.37)
PWM_Bridge_1: Pg2 (R28.1 R37.1 TP12.1 TP17.1), Pg3 (U7.42)
PWM_Bridge_2: Pg2 (R29.1 R36.1 TP14.1 TP15.1), Pg3 (U7.41)
PWM_DAC: Pg1 (R20.1 TP9.1), Pg3 (U7.39)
